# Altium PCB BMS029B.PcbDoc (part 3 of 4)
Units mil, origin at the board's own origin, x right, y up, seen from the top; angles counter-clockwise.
Board outline 4950 x 4000 mil, 4 copper layers (Layer 1 - Top Layer, Layer 2 - GND, Layer 3 - Signal, Layer 4 - Bottom Layer), stack 61.4 mil thick; 370 components, 202 nets, 969 pads, 408 vias.
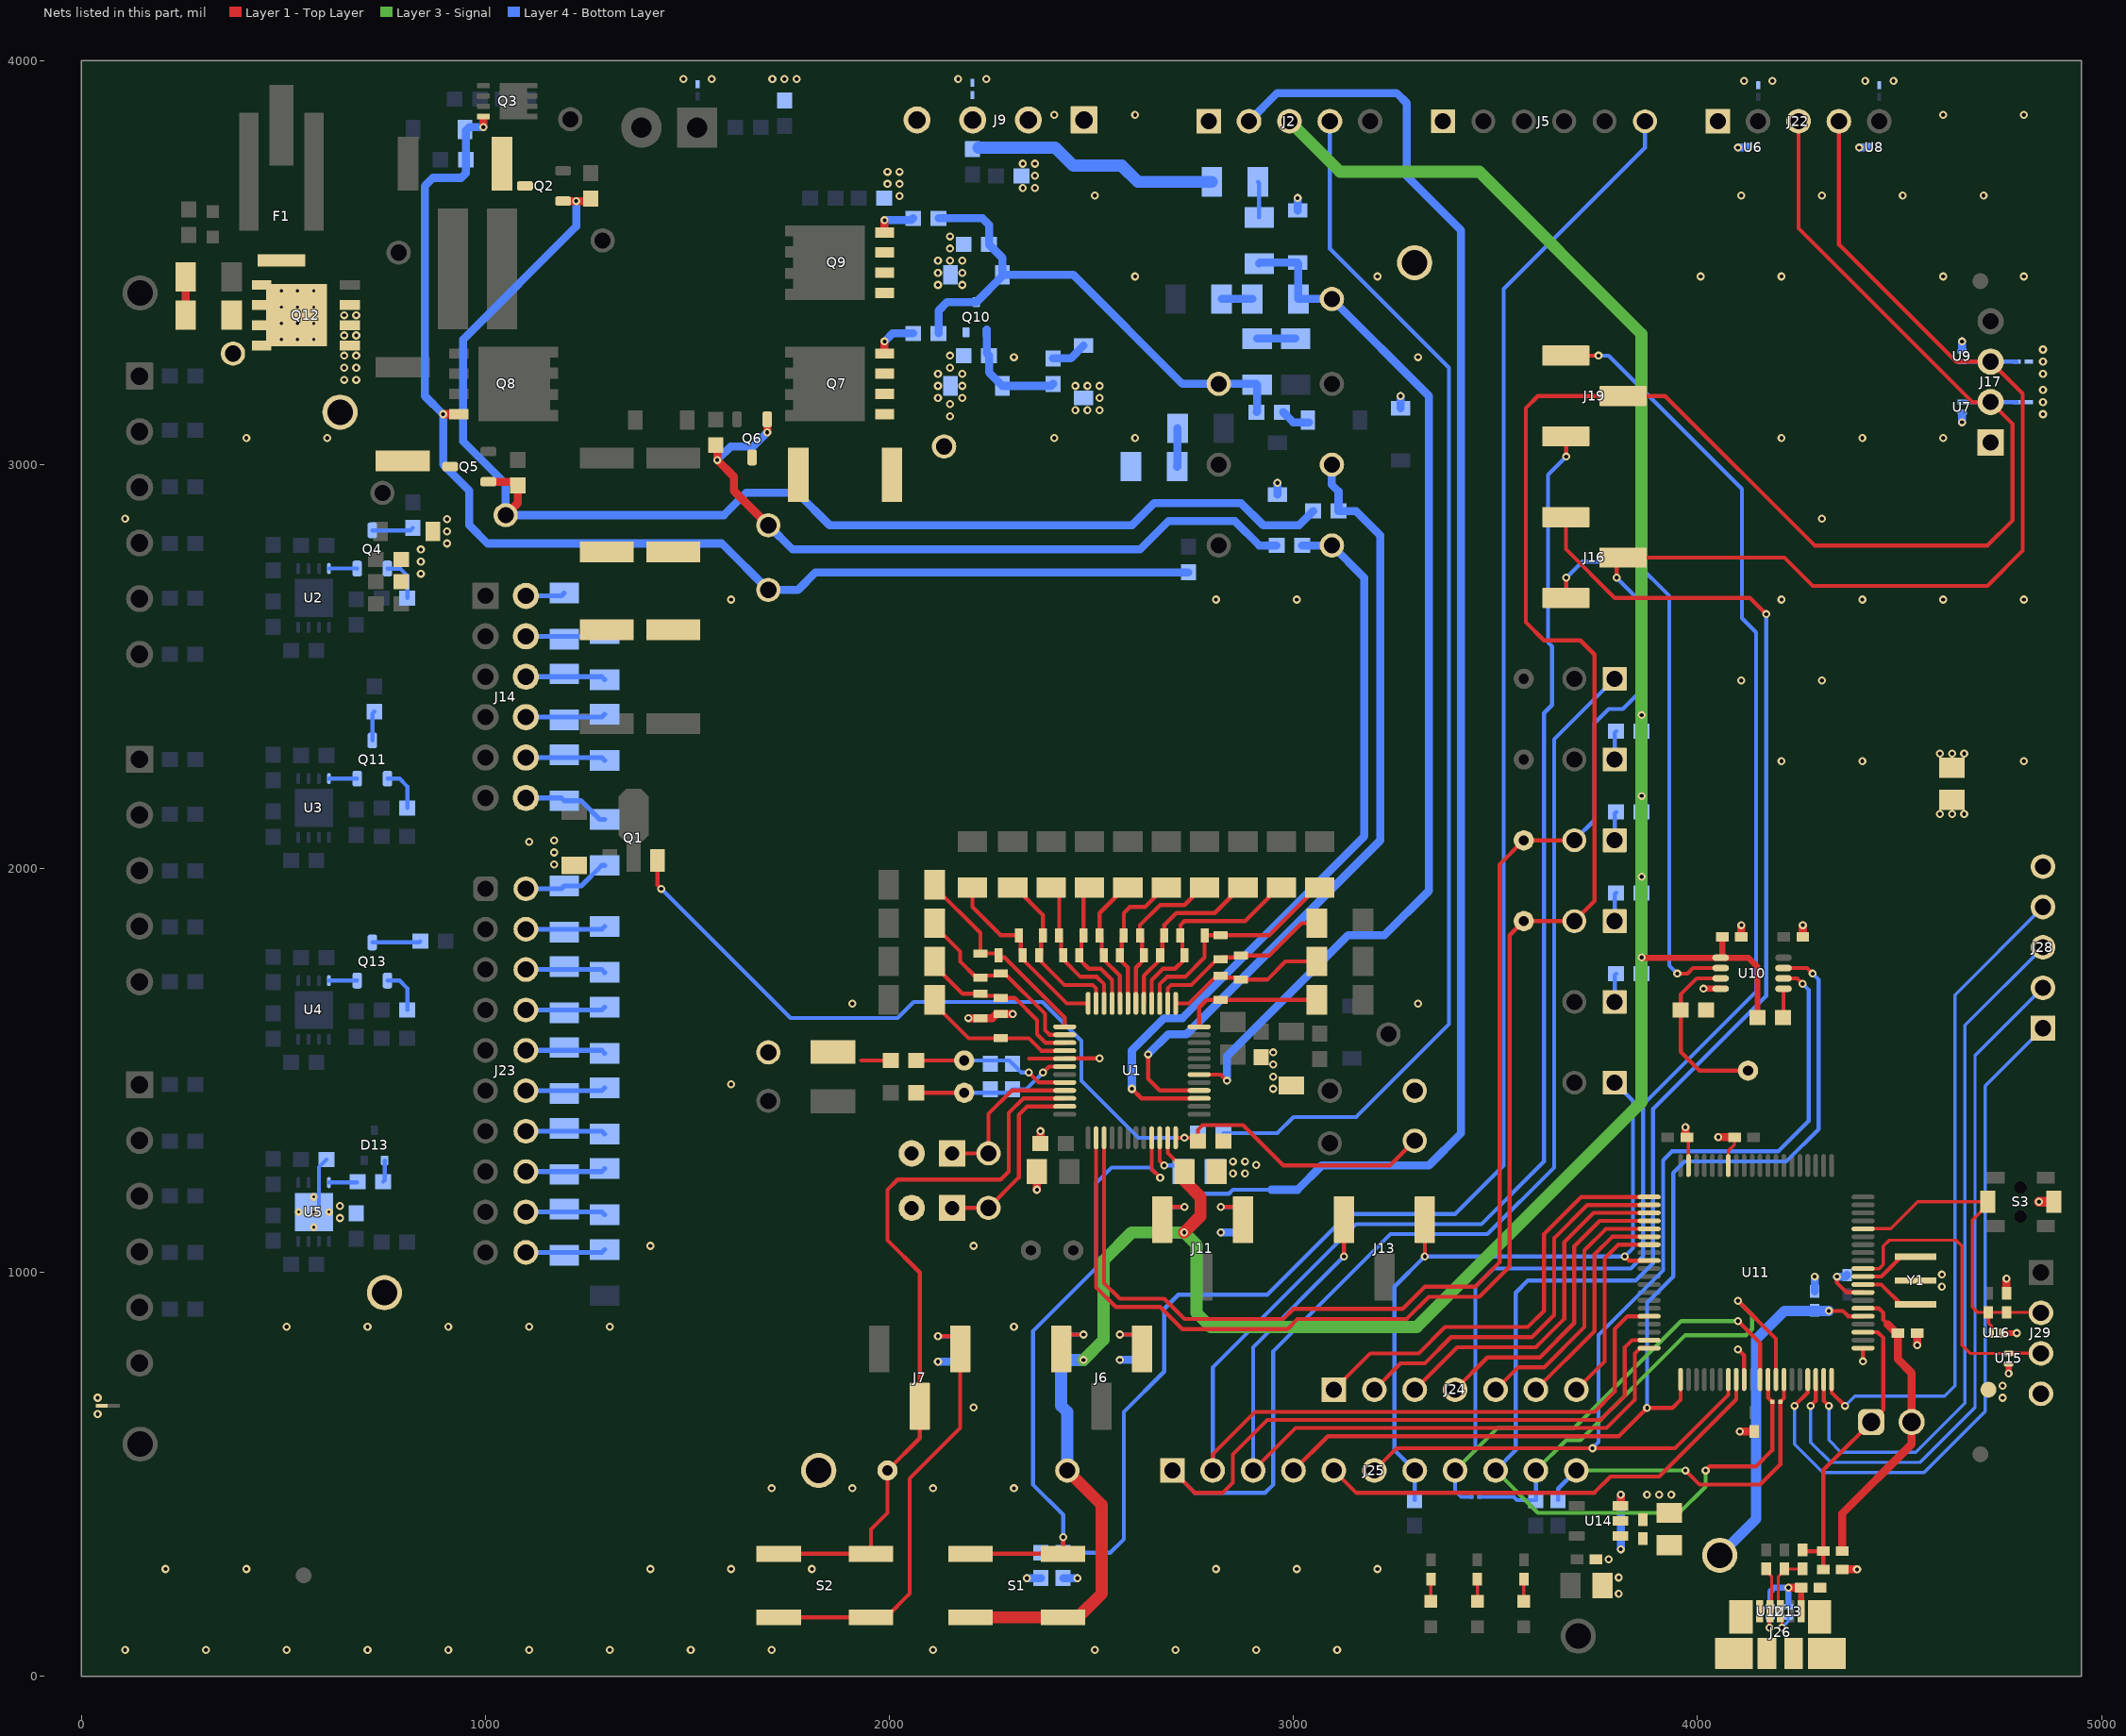
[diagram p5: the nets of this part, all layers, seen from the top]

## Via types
v1: diameter 20, hole 10, Layer 1 - Top Layer to Layer 4 - Bottom Layer, tented both sides, 376 vias
v2: diameter 19.68, hole 7.87, Layer 1 - Top Layer to Layer 4 - Bottom Layer, tented both sides, 32 vias

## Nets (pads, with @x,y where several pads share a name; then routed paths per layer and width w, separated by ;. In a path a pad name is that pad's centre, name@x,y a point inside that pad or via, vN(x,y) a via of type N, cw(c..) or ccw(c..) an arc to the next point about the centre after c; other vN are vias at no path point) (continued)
NetD4_1: D4.1 Q3.4 Q8.4 R50.2 R61.2 TP25.1 | length 3077.7
  Layer 1 - Top Layer w20: v1(895,3125) Q8.4@933.78,3125 ; v1(994.47,3835.53) Q3.4@994.47,3858
  Layer 4 - Bottom Layer w20: v1(994.47,3835.53) 960,3835.53 951.5,3827.03 R50.2@951.5,3755 951.5,3721.5 940,3710 870,3710 850,3690 850,3170 v1(895,3125) 895,3000.35 960,2935.35 960,2850 1005,2805 1585,2805 TP25.1@1700,2690 1773.5,2690 1817.01,2733.5 R61.2@2740,2733.5
NetD5_1: D5.1 Q10.3 R51.2 R55.2 R56.2 R64.2 R65.2 TP28.1 | length 1333.7
  Layer 4 - Bottom Layer w20: R55.2@2121.5,3325 2121.5,3381.5 2142.4,3402.4 Q10.3@2215,3402.4 2279.47,3466.87 D5.1@2279.47,3470 ; R56.2@2121.5,3610 2230,3610 2246.5,3593.5 R51.2@2246.5,3545 2279.47,3512.03 D5.1@2279.47,3470 ; R65.2@2908.5,3130 2910,3131.5 R64.2@2910,3197.91 2907.91,3200 TP28.1@2815,3200 2725,3200 2455,3470 D5.1@2279.47,3470
NetD6_1: D6.1 Q10.1 R52.2 R57.1 | length 283.7
  Layer 4 - Bottom Layer w20: Q10.1@2240.59,3335 2240.59,3275.91 R52.2@2246.5,3270 2246.5,3227.98 D6.1@2279.47,3195 2399.99,3195 R57.1@2405,3200.02
NetD7_1: D7.1 R57.2 | length 88
  Layer 4 - Bottom Layer w20: R57.2@2405,3263.01 2448.54,3263.01 D7.1@2480,3294.47
NetD9_2: D9.2 R65.1 | length 74.4
  Layer 4 - Bottom Layer w20: R65.1@2974.43,3130 2999.43,3105 D9.2@3038.46,3105
NetD13_1: D13.1 R82.2 | length 54.3
  Layer 4 - Bottom Layer w10: R82.2@746.5,1225 750.59,1229.09 D13.1@750.59,1277.6
NetD14_2: D14.2 R120.1 | length 54.9
  Layer 1 - Top Layer w8: D14.2@3340,186.5 R120.1@3340,241.38
NetD15_2: D15.2 R121.1 | length 54.9
  Layer 1 - Top Layer w8: D15.2@3455,186.5 R121.1@3455,241.38
NetD16_2: D16.2 R122.1 | length 54.9
  Layer 1 - Top Layer w8: D16.2@3570,186.5 R122.1@3570,241.38
NetF1_2: F1.2 Q12.5 Q12.6 Q12.7 Q12.8 Q12.9 R48.1 TP24.1
  other v2: 495,3310 535,3310 575,3310 495,3350 535,3350 575,3350 495,3390 535,3390 575,3390 495,3430 535,3430 575,3430
NetJ2_4: J2.4 R15.2 | length 3027.5
  Layer 4 - Bottom Layer w10: R15.2@2826.5,1345 2960,1345 3000,1385 3155,1385 3385,1615 3385,3240 3090,3535 J2.4@3090,3850
NetJ6_1: J6.1 R25.2 | length 112.1
  Layer 1 - Top Layer w10: J6.1@2425.01,841.51 2430,846.5 v1(2480,846.5)
  Layer 4 - Bottom Layer w10: R25.2@2425,846.5 v1(2480,846.5)
NetJ6_3: J6.3 R26.2 | length 112.1
  Layer 1 - Top Layer w10: v1(2570.01,846.5) 2620.01,846.5 J6.3@2625.01,841.51
  Layer 4 - Bottom Layer w10: v1(2570.01,846.5) R26.2@2625.01,846.5
NetJ7_3: J7.3 R29.2 S2.1 S2.2 | length 1128.2
  Layer 1 - Top Layer w10: S2.2@1725.83,146.26 S2.1@1954.17,146.26 1991.26,146.26 2050,205 2050,490 2175,615 J7.3@2175,820.87 ; v1(2120.01,842.37) 2170.01,842.37 J7.3@2175,837.37
  Layer 4 - Bottom Layer w10: v1(2120.01,842.37) R29.2@2175,842.37
NetJ11_1: J11.1 R89.2 | length 138.6
  Layer 1 - Top Layer w10: J11.1@2675,1130.87 2675,1157.37 2680,1162.37 v1(2730,1162.37)
  Layer 4 - Bottom Layer w10: R89.2@2675,1162.37 v1(2730,1162.37)
NetJ11_3: J11.3 R91.2 | length 112.1
  Layer 1 - Top Layer w10: v1(2820.01,1162.37) 2870.01,1162.37 J11.3@2875,1157.37
  Layer 4 - Bottom Layer w10: v1(2820.01,1162.37) R91.2@2875,1162.37
NetJ12_1: J12.1 R92.2 | length 71.5
  Layer 4 - Bottom Layer w10: J12.1@3795,2270 3795,2336.5 R92.2@3798.5,2340
NetJ14_2: J14.2 R87.2 | length 97.9
  Layer 4 - Bottom Layer w12: J14.2@1100,2675 1187.91,2675 R87.2@1195,2682.09
NetJ14_4: J14.4 R87.1 R88.2 | length 197.9
  Layer 4 - Bottom Layer w12: J14.4@1100,2575 1287.91,2575 R88.2@1295,2582.09
NetJ14_6: J14.6 R88.1 R90.2 | length 197.9
  Layer 4 - Bottom Layer w12: J14.6@1100,2475 1287.91,2475 R88.1@1295,2467.91
NetJ14_8: J14.8 R90.1 R93.2 | length 197.9
  Layer 4 - Bottom Layer w12: J14.8@1100,2375 1287.91,2375 R93.2@1295,2382.09
NetJ14_10: J14.10 R93.1 R95.2 | length 197.9
  Layer 4 - Bottom Layer w12: J14.10@1100,2275 1287.91,2275 R93.1@1295,2267.91
NetJ14_12: J14.12 R95.1 R96.2 | length 216.9
  Layer 4 - Bottom Layer w12: J14.12@1100,2175 1187.91,2175 R95.1@1195,2167.91 1237.09,2167.91 1282.91,2122.09 R96.2@1295,2122.09
NetJ15_1: J15.1 R94.2 | length 71.5
  Layer 4 - Bottom Layer w10: J15.1@3795,2070 3795,2136.5 R94.2@3798.5,2140
NetJ18_1: J18.1 R97.2 | length 71.5
  Layer 4 - Bottom Layer w10: J18.1@3795,1870 3795,1936.5 R97.2@3798.5,1940
NetJ20_1: J20.1 R99.2 | length 71.5
  Layer 4 - Bottom Layer w10: J20.1@3795,1670 3795,1736.5 R99.2@3798.5,1740
NetJ23_2: J23.2 R96.1 R98.2 | length 219
  Layer 4 - Bottom Layer w12: J23.2@1100,1950 1187.91,1950 R98.2@1195,1957.09 1237.09,1957.09 1287.91,2007.91 R96.1@1295,2007.91
NetJ23_4: J23.4 R98.1 R100.2 | length 197.9
  Layer 4 - Bottom Layer w12: J23.4@1100,1850 1287.91,1850 R100.2@1295,1857.09
NetJ23_6: J23.6 R100.1 R101.2 | length 197.9
  Layer 4 - Bottom Layer w12: J23.6@1100,1750 1287.91,1750 R100.1@1295,1742.91
NetJ23_8: J23.8 R101.1 R102.2 | length 197.9
  Layer 4 - Bottom Layer w12: J23.8@1100,1650 1287.91,1650 R102.2@1295,1657.09
NetJ23_10: J23.10 R102.1 R103.2 | length 197.9
  Layer 4 - Bottom Layer w12: J23.10@1100,1550 1287.91,1550 R102.1@1295,1542.91
NetJ23_12: J23.12 R103.1 R104.2 | length 197.9
  Layer 4 - Bottom Layer w12: J23.12@1100,1450 1287.91,1450 R104.2@1295,1457.09
NetJ23_14: J23.14 R104.1 R105.2 | length 197.9
  Layer 4 - Bottom Layer w12: J23.14@1100,1350 1287.91,1350 R104.1@1295,1342.91
NetJ23_16: J23.16 R105.1 R106.2 | length 197.9
  Layer 4 - Bottom Layer w12: J23.16@1100,1250 1287.91,1250 R106.2@1295,1257.09
NetJ23_18: J23.18 R106.1 R107.2 | length 197.9
  Layer 4 - Bottom Layer w12: J23.18@1100,1150 1287.91,1150 R106.1@1295,1142.91
NetJ23_20: J23.20 R107.1 R108.2 | length 197.9
  Layer 4 - Bottom Layer w12: J23.20@1100,1050 1287.91,1050 R108.2@1295,1057.09
NetJ24_1: J24.1 U11.21 | length 1089.1
  Layer 1 - Top Layer w10: J24.1@3100,710 3190,800 3310,800 3375,865 3580,865 3620,905 3620,1095 3712.01,1187.01 U11.21@3880.24,1187.01
NetJ24_2: J24.2 U11.22 | length 981
  Layer 1 - Top Layer w10: J24.2@3200,710 3265,775 3325,775 3390,840 3590,840 3645,895 3645,1085 3727.32,1167.32 U11.22@3880.24,1167.32
NetJ24_3: J24.3 U11.23 | length 872.8
  Layer 1 - Top Layer w10: J24.3@3300,710 3405,815 3600,815 3670,885 3670,1075 3742.64,1147.64 U11.23@3880.24,1147.64
NetJ24_4: J24.4 U11.24 | length 764.7
  Layer 1 - Top Layer w10: J24.4@3400,710 3480,790 3610,790 3695,875 3695,1065 3757.95,1127.95 U11.24@3880.24,1127.95
NetJ24_5: J24.5 U11.25 | length 656.5
  Layer 1 - Top Layer w10: J24.5@3500,710 3555,765 3620,765 3720,865 3720,1055 3773.27,1108.27 U11.25@3880.24,1108.27
NetJ24_6: J24.6 U11.26 | length 548.3
  Layer 1 - Top Layer w10: J24.6@3600,710 3745,855 3745,1045 3788.58,1088.58 U11.26@3880.24,1088.58
NetJ24_7: J24.7 U11.27 | length 478.3
  Layer 1 - Top Layer w10: J24.7@3700,710 3770,780 3770,1035 3803.9,1068.9 U11.27@3880.24,1068.9
NetJ26_2: J26.2 R114.1 U12.1 | length 180.7
  Layer 1 - Top Layer w7: R114.1@4170,266.38 4170,261 4184,247 4184,166.4 J26.2@4179.41,161.81 ; v1(4178,120.78) J26.2@4178,162
  Layer 4 - Bottom Layer w7: v1(4178,120.78) 4178,145.2 U12.1@4180,147.2
NetJ26_3: J26.3 R115.1 R116.2 U13.1 | length 232.1
  Layer 1 - Top Layer w7: J26.3@4205,161.81 4200,166.81 4200,247 4215,262 R115.1@4215,266.38 R116.2@4260,266.38 ; v1(4209,120.78) J26.3@4209,162
  Layer 4 - Bottom Layer w7: v1(4209,120.78) 4225,136.78 U13.1@4225,147.2
NetJ26_6: J26.6 J26.7 J26.8 J26.9 J26.10 J26.11 R117.2
NetJ28_1: J28.1 U11.57 | length 1745.5
  Layer 1 - Top Layer w10: v1(4239.96,670) 4272.95,702.99 U11.57@4272.95,735.24
  Layer 4 - Bottom Layer w8: v1(4239.96,670) 4239.96,575.04 4310,505 4560.71,505 4711.88,656.16 4711.88,1461.88 J28.1@4855,1605
NetJ28_2: J28.2 U11.58 | length 1752.8
  Layer 1 - Top Layer w10: v1(4279.96,670) 4292.64,682.68 U11.58@4292.64,735.24
  Layer 4 - Bottom Layer w8: v1(4279.96,670) 4279.96,580.04 4330,530 4550.36,530 4686.87,666.52 4686.87,1536.87 J28.2@4855,1705
NetJ28_3: J28.3 U11.59 | length 1763.4
  Layer 1 - Top Layer w10: U11.59@4312.32,735.24 4312.32,682.68 v1(4325,670)
  Layer 4 - Bottom Layer w8: v1(4325,670) 4325,585 4355,555 4540,555 4661.88,676.88 4661.88,1611.88 J28.3@4855,1805
NetJ28_4: J28.4 U11.60 | length 1646.8
  Layer 1 - Top Layer w10: U11.60@4332.01,735.24 4332.01,702.99 v1(4365,670)
  Layer 4 - Bottom Layer w8: v1(4365,670) 4389.34,694.34 4611.22,694.34 4636.88,720 4636.88,1686.88 J28.4@4855,1905
NetQ2_1: Q2.1 Q5.1 R35.2 R43.2 R62.2 TP26.1 | length 3281.6
  Layer 1 - Top Layer w20: Q5.1@1007.24,2957.6 1070.91,2957.6 R43.2@1080,2948.5 1080,2905 TP26.1@1050,2875 ; Q2.1@1192.24,3652.6 v1(1224.49,3652.6) R35.2@1260,3652.6
  Layer 4 - Bottom Layer w20: v1(1224.49,3652.6) 1224.49,3589.49 945,3310 945,3057.4 1050,2952.4 TP26.1@1050,2875 1590,2875 1645,2930 1772.09,2930 1852.09,2850 2600,2850 2655,2905 2870,2905 2925,2850 3013.5,2850 R62.2@3048.5,2885
NetQ2_3: Q2.3 R33.2
NetQ4_1: Q4.1 R38.2 | length 111.6
  Layer 4 - Bottom Layer w10: Q4.1@757.4,2742.76 788.97,2742.76 806.5,2725.23 R38.2@806.5,2670
NetQ4_2: Q4.2 U2.8 | length 69.6
  Layer 4 - Bottom Layer w10: U2.8@613,2742.83 682.52,2742.83 Q4.2@682.6,2742.76
NetQ4_3: Q4.3 R44.1 | length 102.6
  Layer 4 - Bottom Layer w10: Q4.3@720,2837.24 813.74,2837.24 R44.1@820,2843.5
NetQ5_3: Q5.3 R39.2
NetQ6_1: Q6.1 R42.2 R63.2 TP27.1 | length 1773.6
  Layer 1 - Top Layer w20: R42.2@1570,3048.5 1573.5,3045 v1(1573.5,3011.5) 1615,2970 1615,2935 TP27.1@1700,2850 ; v1(1697.4,3080) Q6.1@1697.4,3112.24
  Layer 4 - Bottom Layer w20: v1(1573.5,3011.5) 1607.01,3045 1662.4,3045 v1(1697.4,3080) ; TP27.1@1700,2850 1760,2790 2620,2790 2690,2860 2855,2860 2915,2800 R63.2@2958.01,2800
NetQ6_3: Q6.3 R40.1
NetQ7_4: Q7.4 R55.1 | length 109
  Layer 1 - Top Layer w20: Q7.4@1987.8,3275 v1(1987.8,3305)
  Layer 4 - Bottom Layer w20: v1(1987.8,3305) 2007.8,3325 R55.1@2058.5,3325
NetQ9_4: Q9.4 R56.1 | length 102.8
  Layer 1 - Top Layer w20: Q9.4@1987.8,3575 v1(1987.8,3605)
  Layer 4 - Bottom Layer w20: v1(1987.8,3605) 2053.5,3605 R56.1@2058.5,3610
NetQ11_1: Q11.1 R58.2 | length 110.6
  Layer 4 - Bottom Layer w10: Q11.1@757.4,2222.76 787.24,2222.76 806.5,2203.5 R58.2@806.5,2150
NetQ11_2: Q11.2 U3.8 | length 69.5
  Layer 4 - Bottom Layer w10: U3.8@613,2222.83 Q11.2@682.52,2222.83
NetQ11_3: Q11.3 R60.1 | length 73.3
  Layer 4 - Bottom Layer w10: Q11.3@720,2317.24 720,2383.5 R60.1@725,2388.5
NetQ13_1: Q13.1 R79.2 | length 110.6
  Layer 4 - Bottom Layer w10: Q13.1@757.4,1722.76 787.24,1722.76 806.5,1703.5 R79.2@806.5,1650
NetQ13_2: Q13.2 U4.8 | length 69.5
  Layer 4 - Bottom Layer w10: U4.8@613,1722.83 Q13.2@682.52,1722.83
NetQ13_3: Q13.3 R80.1 | length 119.6
  Layer 4 - Bottom Layer w10: Q13.3@720,1817.24 835.75,1817.24 R80.1@838.5,1820
NetR5_1: R5.1 R9.2
NetR6_1: R6.1 R10.2
NetR45_1: R45.1 R48.2 | length 95
  Layer 1 - Top Layer w20: R48.2@257.91,3370 R45.1@257.91,3465
NetR64_1: R64.1 R68.2 | length 95
  Layer 4 - Bottom Layer w20: R64.1@2910,3312.09 R68.2@3005,3312.09
NetR70_1: R70.1 R71.2 | length 75.8
  Layer 4 - Bottom Layer w20: R71.2@2822.09,3410 R70.1@2897.91,3410
NetR73_1: R73.1 R74.2 | length 89.1
  Layer 4 - Bottom Layer w10: R74.2@2912.09,3700 2915,3697.09 R73.1@2915,3612.09
NetR76_1: R76.1 R77.2 | length 95.3
  Layer 4 - Bottom Layer w20: R77.2@2712.09,2995 2712.91,2995.83 R76.1@2712.91,3090
NetR82_1: R82.1 U5.8 | length 69.5
  Layer 4 - Bottom Layer w10: U5.8@613,1222.83 R82.1@682.52,1222.83
NetR112_2: R112.2 TP42.1 U10.3 | length 442.9
  Layer 1 - Top Layer w10: U10.3@4057.24,1728.2 3998.2,1728.2 3958.5,1688.5 3958.5,1546.5 4005,1500 TP42.1@4125,1500
NetR113_2: R113.2 U10.5 | length 72.1
  Layer 1 - Top Layer w10: R113.2@4211.5,1631 4212.76,1632.26 U10.5@4212.76,1702.61
NetRT1_1: RT1.1 TP7.1 U1.21 | length 400.5
  Layer 1 - Top Layer w10: RT1.1@2155,1295 TP7.1@2245,1295 2245,1392.75 2303.04,1450.79 U1.21@2433.66,1450.79
NetRT2_1: RT2.1 TP8.1 U1.23 | length 473.6
  Layer 1 - Top Layer w10: RT2.1@2155,1160 TP8.1@2245,1160 2320,1235 2320,1390 2341.42,1411.42 U1.23@2433.66,1411.42
NetU11_69: U11.69 Y1.1 | length 135.8
  Layer 1 - Top Layer w10: U11.69@4409.76,970.47 4454.53,970.47 4504.06,920.94 Y1.1@4525,920.94
NetU11_70: U11.70 Y1.3 | length 135.5
  Layer 1 - Top Layer w10: U11.70@4409.76,990.16 4455.16,990.16 4504.06,1039.06 Y1.3@4525,1039.06
P4_2: J25.6 U10.6 U11.47 | length 2576.4
  Layer 1 - Top Layer w10: J25.6@3200,510 3255,565 v1(3740,565) 3943.93,565 4076.1,697.18 U11.47@4076.1,735.24 ; U10.6@4212.76,1728.2 4246.8,1728.2 v1(4260,1715)
  Layer 4 - Bottom Layer w10: v1(3740,565) 3755,580 3755,845.24 3915,1005.24 3915,1278.15 3936.85,1300 4200,1300 4275,1375 4275,1700 v1(4260,1715)
P4_3: J25.5 U11.48 | length 1163.6
  Layer 1 - Top Layer w10: J25.5@3100,510 3155,455 3744.72,455 3784.72,495 3905,495 4095.79,685.79 U11.48@4095.79,735.24
PACK: D11.1 R70.2 R73.2 TP33.1 U1.42 | length 2639.6
  Layer 1 - Top Layer w10: U1.42@2766.34,1490.16 2819.84,1490.16 v1(2835,1475)
  Layer 4 - Bottom Layer w20: v1(2835,1475) 2835,1535 3135,1835 3225,1835 3335,1945 3335,3170 TP33.1@3095,3410 R70.2@3012.09,3410 3012.09,3498.44 D11.1@3010,3500.53 2917.62,3500.53 R73.2@2915,3497.91
PACK+: C38.1 C42.1 D5.2 D6.2 E2.1 J9.3 J9.4 Q7.1 Q7.2 Q7.3 Q9.1 Q9.2 Q9.3 Q10.2 R40.2 R51.1 R52.1 R74.1 R77.1 TP22.1 | length 613.1
  Layer 4 - Bottom Layer w30: C42.1@2220.02,3785 2410,3785 2455,3740 2575,3740 2615,3700 R74.1@2797.91,3700
  other v1: 2150,3120 2150,3150 2120,3165 2180,3165 2120,3195 2180,3195 2120,3225 2180,3225 2150,3240 2150,3270 2120,3445 2180,3445 2120,3475 2180,3475 2120,3505 2150,3505 2180,3505 2150,3535 2150,3565 2025,3665 1995,3695 2025,3695 1995,3725 2025,3725
PCHG: R62.1 TP31.1 U1.40 | length 1998.2
  Layer 1 - Top Layer w10: v1(2640,1540) 2640,1480 2669.21,1450.79 U1.40@2766.34,1450.79
  Layer 4 - Bottom Layer w20: v1(2640,1540) 2690,1590 2735,1590 3215,2070 3215,2825 3155,2885 R62.1@3111.5,2885 3111.5,2933.5 3095,2950 TP31.1@3095,3000
PDSG: R63.1 TP32.1 U1.39 | length 1892.4
  Layer 1 - Top Layer w10: v1(2600,1455) 2623.9,1431.1 U1.39@2766.34,1431.1
  Layer 4 - Bottom Layer w20: v1(2600,1455) 2600,1550 2680,1630 2725,1630 3175,2080 3175,2720 TP32.1@3095,2800 R63.1@3021.5,2800
PGND: C36.2 C45.2 D7.2 E1.2 E2.2 E3.2 E4.2 E5.2 E6.2 J9.1 J9.2 J17.1 J22.1 NT5.2 R28.1 R30.1 TP36.1 U6.2 U7.2 U8.2 U9.2 | length 153.5
  Layer 1 - Top Layer w10: 1930,1525 R28.1@2003.5,1525
  Layer 4 - Bottom Layer w20: v1(4100,3785) U6.2@4120,3785 ; v1(4400,3785) U8.2@4420,3785 ; v1(4655,3105) U7.2@4655,3125 ; U9.2@4655,3285 v1(4655,3305)
  other v1: 1908,1666 4808,2266 4600,2285 4630,2285 4660,2285 4608,2666 4808,2666 2408,3066 2608,3066 4608,3066 4855,3125 2460,3135 2490,3135 2520,3135 4855,3155 2520,3165 4855,3185 2460,3195 2490,3195 2520,3195 4855,3225 4855,3255 2308,3266 4855,3285 2608,3466 4008,3466 4208,3466 4608,3466 4808,3466 2508,3666 4108,3666 4308,3666 4508,3666 4708,3666 2330,3685 2360,3685 2360,3715 2330,3745 2360,3745 2408,3866 2608,3866 4608,3866 4808,3866 4115,3950 4185,3950 4415,3950 4485,3950 1490,3955 1560,3955 1710,3955 1740,3955 1770,3955 2170,3955 2240,3955
PUR: J27.1 R116.1 R118.2 R119.1 U11.63 | length 738.6
  Layer 1 - Top Layer w10: R116.1@4263.62,310 R119.1@4311.38,310 ; R118.2@4311.38,265 R119.1@4311.38,310 ; U11.63@4409.76,852.36 4445.79,852.36 4460,838.15 4460,660 4311.38,511.38 R119.1@4311.38,310
QGND: C58.1 C59.1 C60.2 C61.2 C62.2 C63.2 C64.2 C65.2 C66.2 C67.2 C68.2 C69.2 C70.2 J26.5 J28.5 J29.4 NT5.1 R112.1 R117.1 R118.1 S3.1 TP45.1 U10.4 U11.14 U11.19 U11.49 U11.61 U11.68 U12.2 U13.2 U14.2 U15.2 U16.2 Y1.2 | length 1025.6
  Layer 1 - Top Layer w8: C61.2@3973.62,1335 3977.68,1330.94 U11.19@3977.68,1264.76 ; U11.14@4076.1,1264.76 4076.1,1301.1 4091.38,1316.38 C69.2@4091.38,1335
  Layer 1 - Top Layer w10: v1(4100,810) 4115.47,794.53 U11.49@4115.47,735.24 ; v1(4345,990) 4345,975 4369.21,950.79 U11.68@4409.76,950.79 ; v1(4409.76,780) U11.61@4409.76,812.99
  Layer 1 - Top Layer w15: v1(4015,1702.61) U10.4@4057.24,1702.61 ; J26.5@4256.18,161.81 4256.18,219.8 R117.1@4256.38,220 ; U16.2@4759.69,850 v1(4790,850) ; v1(4770,750) U15.2@4770,770
  Layer 1 - Top Layer w20: v1(3970,1360) 3970,1338.62 C61.2@3973.62,1335 ; v1(4051.38,1335) C69.2@4091.38,1335 ; v1(4105,606.38) C68.2@4140,606.38 ; C58.1@4108.62,1831 v1(4108.62,1860) ; v1(4225,220) R117.1@4256.38,220 ; C59.1@4260.62,1831 v1(4260.62,1860) ; R118.1@4358.62,265 v1(4395,265) ; v1(4543.62,820) C60.2@4543.62,850 ; C70.2@4765,948.62 v1(4765,985)
  Layer 1 - Top Layer w25: v1(4845,1175) S3.1@4881.69,1175
  Layer 4 - Bottom Layer w15: U12.2@4180,175 4180,210 4190,220 v1(4225,220) U13.2@4225,175
  Layer 4 - Bottom Layer w20: C66.2@4290,953.62 v1(4290,990) ; v1(4345,990) 4366.38,990 C67.2@4370,993.62
  other v1: 2708,66 2908,66 3108,66 3805,205 3805,245 2808,266 3008,266 3208,266 3780,290 3875,450 3905,450 3935,450 4755,690 4755,720 4605,965 4605,995 4600,2135 4630,2135 4660,2135 4208,2266 4408,2266 4108,2466 4308,2466 4208,2666 4408,2666 4308,2866 4208,3066 4408,3066
REG1: C12.2 C58.2 J2.3 R25.1 R89.1 R92.1 R94.1 R97.1 R99.1 R113.1 S1.3 S1.4 TP6.1 U1.35 U10.1 | length 7043.7
  Layer 1 - Top Layer w10: U1.35@2688.58,1333.66 2688.58,1296.42 2730.55,1254.45 C12.2@2730.55,1226.45 ; v1(3861.5,1780) v1@3862.11,1779.39 ; U10.1@4057.24,1779.39 U10.1@4061.38,1783.52
  Layer 1 - Top Layer w15: v1@3862.11,1779.39 U10.1@4057.24,1779.39 4125.61,1779.39 4148.5,1756.5 R113.1@4148.5,1631 ; U10.1@4061.38,1783.52 C58.2@4061.38,1831
  Layer 1 - Top Layer w30: S1.3@2200.83,146.26 S1.4@2429.17,146.26 2466.26,146.26 2525,205 2525,425 TP6.1@2440,510 ; v1(2729.37,1099.37) 2770,1140 2770,1187 C12.2@2730.55,1226.45
  Layer 3 - Signal w30: v1(2480,783.51) 2530,833.51 2530,1030 2599.37,1099.37 v1(2729.37,1099.37) 2760,1068.75 2760,900 2795,865 3305,865 3861.5,1421.5 v1(3861.5,1780) v1(3861.5,1980) v1(3861.5,2180) v1(3861.5,2380) 3861.5,3323.5 3460,3725 3115,3725 J2.3@2990,3850
  Layer 4 - Bottom Layer w30: TP6.1@2440,510 2440,655 2425.01,669.99 R25.1@2425,783.5 v1(2480,783.51) ; R89.1@2675,1099.37 v1(2729.37,1099.37) ; R99.1@3861.5,1740 v1(3861.5,1780) ; R97.1@3861.5,1940 v1(3861.5,1980) ; R94.1@3861.5,2140 v1(3861.5,2180) ; R92.1@3861.5,2340 v1(3861.5,2380)
REG2: C15.2 J2.2 U1.34 | length 3946.4
  Layer 1 - Top Layer w10: U1.34@2668.9,1333.66 2668.9,1276.1 v1(2680,1265)
  Layer 4 - Bottom Layer w10: v1(2680,1265) 2720,1265 2720,1245 2770,1195 2840,1195 2850,1205 2945,1205
  Layer 4 - Bottom Layer w20: J2.2@2890,3850 2960,3920 3255,3920 3280,3895 3280,3715 3415,3580 3415,1345 3335,1265 3070,1265 3010,1205 2945,1205
REGIN: C13.2 Q1.3 R15.1 TP5.1 U1.36 | length 2455.6
  Layer 1 - Top Layer w10: Q1.3@1430.51,2025 Q1.3@1425.71,2020.2 1425.71,1959.29 v1(1435,1950) ; U1.36@2708.27,1333.66 v1(2730,1333.66) 2754.84,1333.66 C13.2@2763.5,1325 2763.5,1353.5 2775,1365 2875,1365 2975,1265 3238.74,1265 TP5.1@3300,1326.26
  Layer 4 - Bottom Layer w10: v1(1435,1950) 1755,1630 2020,1630 2060,1670 2378.66,1670 2475,1573.66 2475,1475 2616.34,1333.66 v1(2730,1333.66) 2752.17,1333.66 R15.1@2763.5,1345
RST: C70.1 J29.2 R123.1 S3.2 U11.76 U16.1 | length 840.7
  Layer 1 - Top Layer w8: U11.76@4409.76,1108.27 4478.27,1108.27 4545,1175 S3.2@4718.31,1175 4718.31,1168.31 4680,1130 4680,915 4693.62,901.38 R123.1@4720,901.38 ; U16.1@4727.2,850 4727.2,868.11 4720.31,875 4720.31,901.06 R123.1@4720,901.38 ; J29.2@4848.62,901.38 R123.1@4720,901.38
RST_SHUT: C20.1 J5.6 R20.1 S1.1 S1.2 U1.33 | length 6120.2
  Layer 1 - Top Layer w10: S1.1@2200.83,303.74 S1.2@2429.17,303.74 2430,304.57 v1(2430,345) ; U1.33@2649.21,1333.66 2649.21,1255.79 v1(2670,1235)
  Layer 4 - Bottom Layer w10: R20.1@2375,306.5 C20.1@2430,306.5 ; v1(2670,1235) 2645,1260 2550,1260 2511.42,1221.42 2511.42,1011.42 2355,855 2355,475 2430,400 C20.1@2430,306.5 ; J5.6@3870,3850 3870,3785 3520,3435 3520,1265 3400,1145 3135,1145 2935,945 2715,945 2680,910 2680,755 2580,655 2580,340 2546.5,306.5 C20.1@2430,306.5
SCL: E4.1 J17.2 J18.2 J19.2 J22.3 TP40.1 U1.26 U7.1 | length 6674.7
  Layer 1 - Top Layer w10: U1.26@2511.42,1333.66 2511.42,963.58 2560,915 2670,915 2725,860 2985,860 3010,885 3280,885 3335,940 3460,940 3535,1015 3535,1835 TP40.1@3570,1870 J18.2@3695,1870 3745,1920 3745,2530 3710,2565 3620,2565 3575,2610 3575,3140 3605,3170 3920,3170 4290,2800 4717.91,2800 4780,2862.09 4780,3100.58 J17.2@4725.59,3155 4680,3155 4250,3585 J22.3@4250,3850
  Layer 4 - Bottom Layer w10: U7.1@4655,3155 J17.2@4725.59,3155 E4.1@4790,3155
SCL2: J19.3 J25.8 NT3.1 U11.51 | length 4641.8
  Layer 1 - Top Layer w10: J19.3@3674.13,3270 v1(3755,3270) ; v1(4100,880) 4154.84,825.16 U11.51@4154.84,735.24
  Layer 3 - Signal w10: J25.8@3400,510 3505,615 3695,615 3960,880 v1(4100,880)
  Layer 4 - Bottom Layer w10: NT3.1@3440,445 3415,445 3400,460 J25.8@3400,510 3450,560 3450,965 3495,1010 3835,1010 3865,1040 3865,1415.36 4145,1695.36 4145,2585 4110,2620 4110,2940 3780,3270 v1(3755,3270)
SDA: E6.1 J15.2 J16.2 J17.3 J22.4 TP39.1 U1.27 U9.1 | length 5956
  Layer 1 - Top Layer w10: U1.27@2531.1,1333.66 2531.1,973.9 2570,935 2680,935 2730,885 2975,885 3000,910 3270,910 3325,965 3450,965 3510,1025 3510,2010 TP39.1@3570,2070 J15.2@3695,2070 ; J16.2@3795,2770 4215,2770 4285,2700 4717.91,2700 4805,2787.09 4805,3175.58 J17.3@4725.59,3255 4640,3255 4350,3545 J22.4@4350,3850 ; v1(3800,2720) 3800,2754.13 J16.2@3815.87,2770
  Layer 4 - Bottom Layer w10: J15.2@3695,2070 3745,2120 3745,2360 3780,2395 3815,2395 3855,2435 3855,2665 v1(3800,2720) ; U9.1@4655,3255 J17.3@4725.59,3255 E6.1@4790,3255
SDA2: J16.3 J25.9 NT4.1 U11.52 | length 4191.5
  Layer 1 - Top Layer w10: J16.3@3674.13,2870 3674.13,2790.87 3795,2670 4130,2670 v1(4170,2630) ; v1(4020,510) 4030,520 4145,520 4185,560 NT4.1@4185,680 4174.53,690.47 U11.52@4174.53,735.24
  Layer 3 - Signal w10: J25.9@3500,510 3605,405 3955,405 4020,470 v1(4020,510)
  Layer 4 - Bottom Layer w10: J25.9@3500,510 3550,560 3550,950 3580,980 3847.43,980 3890,1022.57 3890,1405 4170,1685 v1(4170,2630)
SMBC1: J25.10 NT3.2 R110.2 U11.53 | length 1215.3
  Layer 1 - Top Layer w10: v1(4100,930) 4194.21,835.79 U11.53@4194.21,735.24
  Layer 3 - Signal w10: J25.10@3600,510 3675,585 3710,585 3970,845 4120,845 4135,860 4135,895 v1(4100,930)
  Layer 4 - Bottom Layer w10: NT3.2@3460,445 3545,445 3553.5,436.5 R110.2@3600,436.5 J25.10@3600,510
SMBD1: J25.11 NT4.2 R109.2 U11.54 | length 846.3
  Layer 1 - Top Layer w10: v1(3970,510) 4005,475 4155,475 4205,525 NT4.2@4205,680 4213.9,688.9 U11.54@4213.9,735.24
  Layer 3 - Signal w10: J25.11@3700,510 v1(3970,510)
  Layer 4 - Bottom Layer w10: R109.2@3655,436.5 3655,465 J25.11@3700,510
SRN: C27.1 C28.2 R28.2 TP13.1 U1.20 | length 389.8
  Layer 1 - Top Layer w10: R28.2@2066.5,1525 TP13.1@2185,1525 ; v1(2345,1495) 2369.53,1470.47 U1.20@2433.66,1470.47
  Layer 4 - Bottom Layer w10: TP13.1@2185,1525 2296.5,1525 C27.1@2305,1516.5 2326.5,1495 v1(2345,1495)
SRP: C27.2 C28.1 R27.2 TP12.1 U1.18 | length 394
  Layer 1 - Top Layer w10: R27.2@2066.5,1445 TP12.1@2185,1445 ; v1(2380,1495) 2394.84,1509.84 U1.18@2433.66,1509.84
  Layer 4 - Bottom Layer w10: TP12.1@2185,1445 2296.5,1445 C27.2@2305,1453.5 2338.5,1453.5 v1(2380,1495)
TEST: J29.3 U11.71 U15.1 | length 755
  Layer 1 - Top Layer w8: U11.71@4409.76,1009.84 4449.84,1009.84 4460,1020 4460,1065 4475,1080 4640,1080 4655,1065 4655,820 4675.31,799.69 U15.1@4775,799.69 ; U15.1@4775.31,800 J29.3@4850,800
TS2: J7.2 S2.3 S2.4 TP11.1 U1.22 | length 1830.1
  Layer 1 - Top Layer w10: S2.4@1725.83,303.74 S2.3@1954.17,303.74 1954.17,364.17 1995,405 TP11.1@1995,510 2075,590 J7.2@2075,669.14 2075,1000 1995,1080 1995,1205 2020,1230 2275,1230 2295,1250 2295,1395 2331.1,1431.1 U1.22@2433.66,1431.1
uC_HDQ: J13.3 J21.1 J25.7 R111.2 U11.29 | length 1762.6
  Layer 1 - Top Layer w10: v1(3325,1040) J13.3@3325,1130.87 ; v1(3820,1040) 3830.47,1029.53 U11.29@3880.24,1029.53
  Layer 4 - Bottom Layer w10: R111.2@3300,436.5 J25.7@3300,510 3250,560 3250,965 v1(3325,1040) v1(3820,1040) 3840,1060 3840,1425 J21.1@3795,1470
uC_SPI_CLK: J19.1 J25.2 U11.36 | length 4465.3
  Layer 1 - Top Layer w10: J25.2@2800,510 2800,550 2905,655 3745,655 3795,705 3795,860 3826.73,891.73 U11.36@3880.24,891.73 ; J19.1@3674.13,3070 3675,3069.13 v1(3675,3020)
  Layer 4 - Bottom Layer w10: J25.2@2800,510 2800,765 3155,1120 3465,1120 3620,1275 3620,2385 3640,2405 3640,2550 3630,2560 3630,2975 v1(3675,3020)
uC_SPI_CS: J10.1 J25.1 U11.39 | length 4237.6
  Layer 1 - Top Layer w10: J25.1@2700,510 2755,455 2825,455 2850,480 2850,550 2935,635 3760,635 3820,695 3820,815 3837.68,832.68 U11.39@3880.24,832.68
  Layer 4 - Bottom Layer w10: J25.1@2700,510 2755,455 2930,455 2950,475 2950,805.28 3239.72,1095 3480,1095 3645,1260 3645,2320 J10.1@3795,2470
uC_SPI_MISO_A: J16.1 U10.2 | length 1413.4
  Layer 1 - Top Layer w10: J16.1@3674.13,2670 3675,2670.87 v1(3675,2720) ; v1(3950,1740) 3975,1740 3988.8,1753.8 U10.2@4057.24,1753.8
  Layer 4 - Bottom Layer w10: v1(3675,2720) 3715,2760 3845,2760 3930,2675 3930,1760 v1(3950,1740)
uC_SPI_MISO_B: J25.4 U10.7 U11.41 | length 2563.4
  Layer 1 - Top Layer w10: J25.4@3000,510 3085,595 3805,595 v1(3875,665) 3937.99,665 3957.99,685 U11.41@3957.99,735.24 ; U10.7@4212.76,1753.8 4271.2,1753.8 v1(4285,1740)
  Layer 4 - Bottom Layer w10: v1(3875,665) 3875,925.47 3940,990.47 3940,1246.77 3968.23,1275 4220,1275 4300,1355 4300,1725 v1(4285,1740)
uC_SPI_MOSI: J13.1 J25.3 U11.40 | length 1887.2
  Layer 1 - Top Layer w10: J25.3@2900,510 3005,615 3775,615 3845,685 3845,800 3857.99,812.99 U11.40@3880.24,812.99 ; v1(3125,1040) J13.1@3125,1130.87
  Layer 4 - Bottom Layer w10: J25.3@2900,510 2900,815 v1(3125,1040)
VBUS: C62.1 C63.1 C66.1 J26.1 TP43.1 U11.65 U14.1 U14.3 | length 1034.5
  Layer 1 - Top Layer w10: v1(4325,905) 4360,905 4373.27,891.73 U11.65@4409.76,891.73
  Layer 1 - Top Layer w20: U14.3@3809.13,422.4 3810,423.27 v1(3810,450)
  Layer 4 - Bottom Layer w20: v1(3810,315) v1(3810,450)
  Layer 4 - Bottom Layer w25: TP43.1@4055,300 4145,390 4145,835 4215,905 v1(4325,905)
VC0: C23.1 R24.2 U1.16 | length 380
  Layer 1 - Top Layer w10: R24.2@2112.09,1675 2112.09,1664.17 2196.26,1580 C23.1@2275,1580 2345,1580 2375.79,1549.21 U1.16@2433.66,1549.21
VC1: C22.2 C24.1 R23.2 U1.15 | length 424.6
  Layer 1 - Top Layer w10: R23.2@2112.09,1770 2112.09,1759.17 2181.26,1690 C24.1@2225,1690 2230,1685 C22.2@2270,1685 ; C22.2@2275,1680 2310,1680 2365,1625 2365,1590 2386.1,1568.9 U1.15@2433.66,1568.9
VC2: C21.2 C22.1 R22.2 U1.14 | length 479.7
  Layer 1 - Top Layer w10: R22.2@2112.09,1865 2112.09,1857.91 2175,1795 2175,1770 2215,1730 C21.2@2225,1730 2230,1735 C22.1@2270,1735 ; C22.1@2275,1740 2285.31,1740 2385,1640.31 2385,1600 2396.42,1588.58 U1.14@2433.66,1588.58
VC3: C19.2 C21.1 R21.2 U1.13 | length 514.2
  Layer 1 - Top Layer w10: R21.2@2112.09,1960 2112.09,1953.91 2225,1841 C21.1@2225,1790 2265,1790 C19.2@2270,1785 2275,1780 2285,1780 2433.66,1631.34 U1.13@2433.66,1608.27
VC4: C18.2 C19.1 R19.2 U1.12 | length 455.7
  Layer 1 - Top Layer w10: R19.2@2205,1952.91 2205,1905 2275,1835 C18.2@2320,1835 2325,1830 C19.1@2325,1790 ; C19.1@2330,1785 2330,1775 2438.66,1666.34 U1.12@2491.73,1666.34
VC5: C17.2 C18.1 R18.2 U1.11 | length 418.4
  Layer 1 - Top Layer w10: R18.2@2305,1952.91 2312.09,1952.91 2380,1885 C18.1@2380,1835 2375,1830 C17.2@2375,1790 ; C17.2@2370,1785 2370,1775 2433,1712 2503,1712 2511.42,1703.58 U1.11@2511.42,1666.34
VC6: C16.2 C17.1 R17.2 U1.10 | length 357.2
  Layer 1 - Top Layer w10: R17.2@2400,1952.91 2420,1932.91 C16.2@2420,1835 2425,1830 C17.1@2425,1790 ; C17.1@2430,1785 2430,1775 2473,1732 2513,1732 2531.1,1713.9 U1.10@2531.1,1666.34
VC7: C14.2 C16.1 R16.2 U1.9 | length 340.9
  Layer 1 - Top Layer w10: C14.2@2470,1785 2470,1775 2493,1752 2523,1752 2550.79,1724.21 U1.9@2550.79,1666.34 ; C14.2@2475,1790 2475,1830 C16.1@2480,1835 2480,1937.91 R16.2@2495,1952.91
VC8: C11.2 C14.1 R14.2 U1.8 | length 333.6
  Layer 1 - Top Layer w10: C14.1@2525,1790 2525,1830 C11.2@2520,1835 2520,1890 2582.91,1952.91 R14.2@2590,1952.91 ; C14.1@2530,1785 2530,1775 2570.47,1734.53 U1.8@2570.47,1666.34
VC9: C10.2 C11.1 R13.2 U1.7 | length 360.1
  Layer 1 - Top Layer w10: C10.2@2570,1785 2570,1775 2590.16,1754.84 U1.7@2590.16,1666.34 ; C10.2@2575,1790 2575,1830 C11.1@2580,1835 2580,1890 2595,1905 2632.52,1905 2680.43,1952.91 R13.2@2685,1952.91
VC10: C9.2 C10.1 R12.2 U1.6 | length 397.6
  Layer 1 - Top Layer w10: U1.6@2609.84,1666.34 2609.84,1754.53 2630,1774.69 C10.1@2630,1785 ; C10.1@2625,1790 2625,1830 C9.2@2620,1835 2620,1860 2670,1910 2730,1910 2772.91,1952.91 R12.2@2780,1952.91
VC11: C8.2 C9.1 R11.2 U1.5 | length 441
  Layer 1 - Top Layer w10: U1.5@2629.53,1666.34 2629.53,1734.53 2670,1775 C8.2@2670,1785 ; C8.2@2675,1790 2675,1830 C9.1@2680,1835 2680,1860 2710,1890 2805,1890 2867.91,1952.91 R11.2@2875,1952.91
VC12: C7.2 C8.1 R8.2 U1.4 | length 530.3
  Layer 1 - Top Layer w10: U1.4@2649.21,1666.34 2649.21,1724.21 2677,1752 2707,1752 2730,1775 C8.1@2730,1785 ; C8.1@2725,1790 2725,1830 C7.2@2720,1835 2720,1860 2730,1870 2880,1870 2962.91,1952.91 R8.2@2970,1952.91
VC13: C6.2 C7.1 R7.2 U1.3 | length 574.9
  Layer 1 - Top Layer w10: U1.3@2668.9,1666.34 2668.9,1713.9 2687,1732 2732,1732 2780,1780 C7.1@2780,1835 C6.2@2820,1835 2940,1835 3057.91,1952.91 R7.2@3065,1952.91
VC14: C5.2 C6.1 R4.2 U1.2 | length 466.4
  Layer 1 - Top Layer w10: U1.2@2688.58,1666.34 2688.58,1703.58 2697,1712 2747,1712 2810,1775 C6.1@2820,1775 ; C6.1@2825,1780 2865,1780 C5.2@2870,1785 2940,1785 3020,1865 R4.2@3057.91,1865
VC15: C4.2 C5.1 R3.2 U1.1 | length 393.8
  Layer 1 - Top Layer w10: U1.1@2708.27,1666.34 2741.34,1666.34 2810,1735 C4.2@2820,1735 ; C4.2@2825,1730 2865,1730 C5.1@2870,1725 2935,1725 2980,1770 R3.2@3057.91,1770
VC16: C4.1 R2.2 U1.48 | length 347.4
  Layer 1 - Top Layer w10: U1.48@2766.34,1608.27 2766.34,1656.34 2785,1675 C4.1@2820,1675 R2.2@3057.91,1675
VSS: C1.2 C2.2 C12.1 C13.1 C15.1 C20.2 C23.2 C24.2 C25.1 C26.2 C47.1 C54.1 C57.1 C71.2 D8.2 D10.2 D11.2 D12.2 J2.1 J5.1 NT1.1 Q12.1 Q12.2 Q12.3 R20.2 R26.1 R29.1 R66.1 R91.1 RT1.2 RT2.2 TP14.1 TP15.1 TP16.1 TP17.1 TP18.1 U1.17 U5.7 U5.9 | length 832.5
  Layer 1 - Top Layer w10: 2345.47,1529.53 U1.17@2433.66,1529.53 2434.13,1530 v1(2520,1530)
  Layer 1 - Top Layer w20: v1(2195,1630) C24.2@2225,1630 2255,1630 2265,1640 C23.2@2275,1640 v1(2305,1640) ; v1(2365,1205) C25.1@2365,1250 ; C26.2@2373.5,1320 v1(2373.5,1350)
  Layer 4 - Bottom Layer w10: v2(575,1150) 587.8,1162.8 587.8,1187.4 587.8,1261.3 C57.1@606.5,1280
  Layer 4 - Bottom Layer w20: v1(2120,779.37) R29.1@2175,779.37 ; v1(2340,243.5) R20.2@2375,243.5 ; C20.2@2430,243.5 v1(2465,243.5) ; v1(2570,783.51) R26.1@2625.01,783.51 ; v1(2820,1099.37) R91.1@2875,1099.37 ; D12.2@2960,2925.53 v1(2960,2955) ; D11.2@3010,3629.47 v1(3010,3660) ; D10.2@3265,3139.47 v1(3265,3170)
  other v1: 108,66 308,66 508,66 708,66 908,66 1108,66 1308,66 1508,66 1708,66 2108,66 2508,66 208,266 408,266 1408,266 1608,266 1808,266 1708,466 1908,466 2108,466 2308,466 40,650 2208,666 40,690 508,866 708,866 908,866 1108,866 1308,866 2308,866 1408,1066 2208,1066 640,1135 640,1165 2850,1245 2880,1245 2908,1266 2850,1275 2880,1275 2950,1455 1608,1466 2950,1485 2950,1515 2950,1545 3308,1666 1170,2010 1170,2040 1108,2066 1170,2070 1608,2666 2808,2666 3008,2666 840,2730 840,2760 840,2790 905,2805 905,2835 905,2865 108,2866 408,3066 608,3066 650,3210 680,3210 650,3240 680,3240 3308,3266 650,3270 680,3270 650,3320 680,3320 650,3370 680,3370 3208,3466
  other v2: 575,1112.6 537.6,1150 612.4,1150 575,1187.4
VUSB: C60.1 J27.2 R119.2 U11.66 | length 747.3
  Layer 1 - Top Layer w10: U11.66@4409.76,911.42 4448.58,911.42 4460,900 4460,882.44 4470.79,871.65
  Layer 1 - Top Layer w20: R119.2@4358.62,310 4358.62,403.62 4530,575 J27.2@4530,630 4530,751.38 4496.38,785 C60.1@4496.38,850 4492.44,850 4470.79,871.65
pads on no net: D13.2 FID1.1 FID2.1 FID3.1 FID4.1 FID5.1 FID6.1 H1.0 H2.0 H3.0 H4.0 J17.4 J26.4 J29.1 S3.MH1 S3.MH2 S3.MP1 S3.MP2 S3.MP3 S3.MP4 SH-J1.0 SH-J2.0 SH-J3.0 SH-J4.0 SH-J5.0 SH-J6.0 SH-J7.0 SH-J8.0 SH-J9.0 SH-J10.0 SH-J11.0 SH-J12.0 SH-J13.0 SH-J14.0 SH-J15.0 SH-J16.0 SH-J17.0 SH-J18.0 SH-J19.0 SH-J20.0 SH-J21.0 U1.19 U1.44 U6.1S U6.2S U7.1S U7.2S U8.1S U8.2S U9.1S U9.2S U11.1 U11.2 U11.3 U11.4 U11.5 U11.6 U11.7 U11.8 U11.9 U11.10 U11.12 U11.13 U11.28 U11.30 U11.31 U11.32 U11.33 U11.34 U11.35 U11.37 U11.38 U11.42 U11.43 U11.44 U11.45 U11.46 U11.55 U11.56 U11.72 U11.73 U11.74 U11.75 U11.77 U11.78 U11.79 U11.80 U12.1S U12.2S U13.1S U13.2S U14.4 U15.1S U15.2S U16.1S U16.2S

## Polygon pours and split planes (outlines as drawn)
VSS on Layer 3 - Signal "Layer 3 - PWR - VSS" (solid, remove dead copper, pour order 10): 20,20 2610,20 2610,940 3570,940 3570,1410 3900,1410 3900,3805 3420,3805 3420,3885 3240,3885 3240,3800 2840,3800 2840,3885 2735,3885 2735,3805 2735,2785 2555,2605 1980,2030 1980,2000 1980,1660 1960,1640 1950,1630 1950,1575 1950,1470 1635,1470 1565,1540 1470,1635 1470,1735 1470,2195 2265,2990 2265,3180 2265,3890 1460,3890 1460,3975 1460,3980 20,3980
PGND on Layer 3 - Signal "Layer 3 - PWR - PGND" (solid, remove dead copper, pour order 12): 1850,1500 1650,1500 1615,1535 1500,1650 1500,1845 1500,2195 1745,2440 2285,2980 2285,3850 2285,3905 1480,3905 1480,3980 4930,3980 4930,2225 4500,2225 4500,3295 3920,3295 3920,3905 2705,3905 2705,2805 1920,2020 1920,1500
3.3V on Layer 3 - Signal "Layer 3 - PWR - 3.3V" (solid, remove dead copper, pour order 26): 3250,30 4920,30 4920,2100 3960,2100 3960,1420 4015,1365 4075,1365 4155.03,1284.97 4155.03,1195 4155.03,767.53 4052.5,665 4052.5,462.5 3955,365 3635,365 3250,365
VSS on Layer 2 - GND "Layer 2 - GND - VSS" (solid, remove dead copper, pour order 8): 20,20 2610,20 2610,940 3570,940 3570,1410 3900,1410 3900,3805 3420,3805 3420,3885 3240,3885 3240,3800 2840,3800 2840,3885 2735,3885 2735,3805 2735,2785 2555,2605 1980,2030 1980,2000 1980,1660 1960,1640 1950,1630 1950,1575 1950,1470 1635,1470 1565,1540 1470,1635 1470,1735 1470,2195 2265,2990 2265,3180 2265,3890 1460,3890 1460,3975 1460,3980 20,3980
QGND on Layer 2 - GND "Layer 2 - GND - QGND" (solid, remove dead copper, pour order 6): 4925,2195 4470,2195 4470,3265 3930,3265 3930,1380 3600,1380 3600,910 2630,910 2630,20 4930,20 4930,2195
PGND on Layer 2 - GND "Layer 2 - GND - PGND" (solid, remove dead copper, pour order 2): 1850,1500 1650,1500 1615,1535 1500,1650 1500,1845 1500,2195 1745,2440 2285,2980 2285,3850 2285,3905 1480,3905 1480,3980 4930,3980 4930,2225 4500,2225 4500,3295 3920,3295 3920,3905 2705,3905 2705,2805 1920,2020 1920,1500
VSS on Layer 1 - Top Layer "Layer 1 - Top Layer - VSS" (solid, remove dead copper, pour order 14): 20,20 2610,20 2610,940 3570,940 3570,1410 3900,1410 3900,3805 3420,3805 3420,3885 3240,3885 3240,3800 2840,3800 2840,3885 2735,3885 2735,3805 2735,2785 2555,2605 1980,2030 1980,2000 1980,1660 1960,1640 1950,1630 1950,1575 1950,1470 1635,1470 1565,1540 1470,1635 1470,1735 1470,2195 2265,2990 2265,3180 2265,3890 1460,3890 1460,3975 1460,3980 20,3980
QGND on Layer 1 - Top Layer "Layer 1 - Top Layer - QGND" (solid, remove dead copper, pour order 18): 4925,2195 4470,2195 4470,3265 3930,3265 3930,1380 3600,1380 3600,910 2630,910 2630,20 4930,20 4930,2195
PGND on Layer 1 - Top Layer "Layer 1 - Top Layer - PGND" (solid, remove dead copper, pour order 16): 1850,1500 1650,1500 1615,1535 1500,1650 1500,1845 1500,2195 1745,2440 2285,2980 2285,3850 2285,3905 1480,3905 1480,3980 4930,3980 4930,2225 4500,2225 4500,3295 3920,3295 3920,3905 2705,3905 2705,2805 1920,2020 1920,1500
VSS on Layer 4 - Bottom Layer "Layer 4 - Bottom Layer - VSS" (solid, remove dead copper, pour order 24): 20,20 2610,20 2610,940 3570,940 3570,1410 3900,1410 3900,3805 3420,3805 3420,3885 3240,3885 3240,3800 2840,3800 2840,3885 2735,3885 2735,3805 2735,2785 2555,2605 1980,2030 1980,2000 1980,1660 1960,1640 1950,1630 1950,1575 1950,1470 1635,1470 1565,1540 1470,1635 1470,1735 1470,2195 2265,2990 2265,3180 2265,3890 1460,3890 1460,3975 1460,3980 20,3980
PGND on Layer 4 - Bottom Layer "Layer 4 - Bottom Layer - PGND" (solid, remove dead copper, pour order 22): 1850,1500 1650,1500 1615,1535 1500,1650 1500,1845 1500,2195 1745,2440 2285,2980 2285,3850 2285,3905 1480,3905 1480,3980 4930,3980 4930,2225 4500,2225 4500,3295 3920,3295 3920,3905 2705,3905 2705,2805 1920,2020 1920,1500
QGND on Layer 4 - Bottom Layer "Layer 4 - Bottom Layer - QGND" (solid, remove dead copper, pour order 20): 4925,2195 4470,2195 4470,3265 3930,3265 3930,1380 3600,1380 3600,910 2630,910 2630,20 4930,20 4930,2195

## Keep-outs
Keep-Out Layer:
  text ".Layer_Name" at 577,-858.49 h60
